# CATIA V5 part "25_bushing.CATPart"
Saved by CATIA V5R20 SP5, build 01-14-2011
Part number: 25_bushing
Bounding box of the stored display mesh (mm): x -11.017 to 11.017, y -37 to -7, z -11.009 to 11.009
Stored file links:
  C:\Documents and Settings\anizard\Bureau\13\25_bushing.CATPart
  C:\Documents and Settings\anizard\Bureau\13\anizard.CATProduct
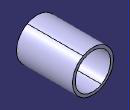
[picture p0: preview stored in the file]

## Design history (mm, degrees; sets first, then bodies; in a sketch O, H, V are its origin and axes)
Set1
  Plane1 to Plane3: linked copy from another document
  Point1: linked copy from another document
  Line1: linked copy from another document
Body1 (main body)
  Sketch1 on Plane1, origin (0, 0, 0), H (0, 1, 0), V (0, 0, 1)
    line L1 (-37, 11.025) -> (-7, 11.025)
    line L2 (-7, 11.025) -> (-7, 9.525)
    line L3 (-7, 9.525) -> (-37, 9.525)
    line L4 (-37, 9.525) -> (-37, 11.025)
    reference intersected line E1 through (-37, 0) direction (0, 1) from Plane2
    reference intersected line E2 through (-7, 0) direction (0, 1) from Plane3
    reference projected point E3 (0, 9.525) from Point1
    distance L1 L3 = 1.5
    horizontal: L1 H, L3 H
    vertical: L2 V, L4 V
    coincidence: L4 E1, L2 E2, L3 E3
  Shaft1: profile Sketch1, axis Line1, angle 360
